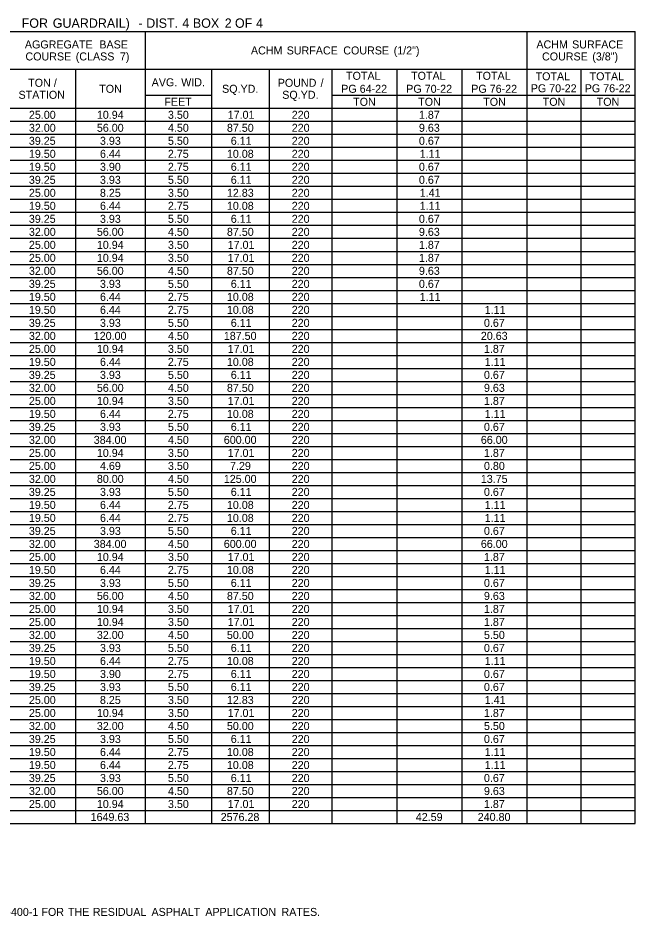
# Model space of a CAD drawing. Extents: x 540541 to 1930787, y -1948574 to 596640.
# Drawn here: x 558293 to 558755, y -1946901 to -1946228 of the extents above; entities that cross this region are included whole.
import ezdxf

# ---------------------------------------------------------------- set-up
doc = ezdxf.new("R2010")
doc.units = 0
doc.layers.add('Default', color=7, linetype='Continuous')

msp = doc.modelspace()

# ---------------------------------------------------------------- linework, layer by layer
at = {"layer": 'Default'}
for p, q in [((557868.72, -1946237.94), (558755.48, -1946237.94)), ((558388.4, -1946831.71), (558388.4, -1946237.94)), ((558674.56, -1946831.71), (558674.56, -1946237.94)), ((558755.48, -1946831.71), (558755.48, -1946237.94)), ((558286.51, -1946266.21), (558755.48, -1946266.21)), ((558336.23, -1946831.71), (558336.23, -1946266.21)), ((558438.12, -1946266.21), (558481.51, -1946266.21)), ((558438.12, -1946831.71), (558438.12, -1946266.21)), ((558481.51, -1946831.71), (558481.51, -1946266.21)), ((558528.31, -1946831.71), (558528.31, -1946266.21)), ((558577.06, -1946831.71), (558577.06, -1946266.21)), ((558625.81, -1946831.71), (558625.81, -1946266.21)), ((558715.02, -1946831.71), (558715.02, -1946266.21)), ((558388.4, -1946285.71), (558438.12, -1946285.71)), ((558388.4, -1946295.46), (558388.4, -1946285.71)), ((558438.12, -1946831.71), (558438.12, -1946285.71)), ((558528.31, -1946285.71), (558625.81, -1946285.71)), ((558625.81, -1946285.71), (558755.48, -1946285.71)), ((558286.51, -1946295.46), (558438.12, -1946295.46)), ((558336.23, -1946831.71), (558336.23, -1946295.46)), ((558438.12, -1946295.46), (558755.48, -1946295.46)), ((558481.51, -1946675.71), (558481.51, -1946295.46)), ((558577.06, -1946831.71), (558577.06, -1946295.46)), ((558625.81, -1946831.71), (558625.81, -1946295.46)), ((558090.05, -1946305.21), (558755.48, -1946305.21)), ((558090.05, -1946314.96), (558755.48, -1946314.96)), ((558090.05, -1946324.71), (558755.48, -1946324.71)), ((558040.32, -1946334.46), (558755.48, -1946334.46)), ((558090.05, -1946344.21), (558755.48, -1946344.21)), ((558090.05, -1946353.96), (558755.48, -1946353.96)), ((557868.72, -1946363.71), (558528.31, -1946363.71)), ((558090.05, -1946363.71), (558755.48, -1946363.71)), ((558090.05, -1946373.46), (558755.48, -1946373.46)), ((558090.05, -1946383.21), (558755.48, -1946383.21)), ((558090.05, -1946392.96), (558755.48, -1946392.96)), ((558040.32, -1946402.71), (558755.48, -1946402.71)), ((558090.05, -1946412.46), (558755.48, -1946412.46)), ((558090.05, -1946422.21), (558755.48, -1946422.21)), ((558090.05, -1946431.96), (558755.48, -1946431.96)), ((557868.72, -1946441.71), (558481.51, -1946441.71)), ((558040.32, -1946441.71), (558528.31, -1946441.71)), ((558481.51, -1946441.71), (558755.48, -1946441.71)), ((558090.05, -1946451.46), (558755.48, -1946451.46)), ((558090.05, -1946461.21), (558755.48, -1946461.21)), ((558090.05, -1946470.96), (558755.48, -1946470.96)), ((558040.32, -1946480.71), (558755.48, -1946480.71)), ((558090.05, -1946490.46), (558755.48, -1946490.46)), ((558090.05, -1946500.21), (558755.48, -1946500.21)), ((558090.05, -1946509.96), (558755.48, -1946509.96)), ((558040.32, -1946519.71), (558755.48, -1946519.71)), ((558090.05, -1946529.46), (558755.48, -1946529.46)), ((558090.05, -1946539.21), (558755.48, -1946539.21)), ((558090.05, -1946548.96), (558755.48, -1946548.96)), ((558040.32, -1946558.71), (558755.48, -1946558.71)), ((558090.05, -1946568.46), (558755.48, -1946568.46)), ((558090.05, -1946578.21), (558755.48, -1946578.21)), ((558090.05, -1946587.96), (558755.48, -1946587.96)), ((558040.32, -1946597.71), (558388.4, -1946597.71)), ((558336.23, -1946597.71), (558388.4, -1946597.71)), ((558388.4, -1946597.71), (558755.48, -1946597.71)), ((558090.05, -1946607.46), (558755.48, -1946607.46)), ((558090.05, -1946617.21), (558388.4, -1946617.21)), ((558336.23, -1946617.21), (558388.4, -1946617.21)), ((558388.4, -1946617.21), (558755.48, -1946617.21)), ((558090.05, -1946626.96), (558388.4, -1946626.96)), ((558336.23, -1946626.96), (558388.4, -1946626.96)), ((558388.4, -1946626.96), (558755.48, -1946626.96)), ((557868.72, -1946636.71), (558755.48, -1946636.71)), ((558040.32, -1946636.71), (558755.48, -1946636.71)), ((558090.05, -1946646.46), (558755.48, -1946646.46)), ((558090.05, -1946656.21), (558755.48, -1946656.21)), ((558090.05, -1946665.96), (558755.48, -1946665.96)), ((558040.32, -1946675.71), (558755.48, -1946675.71)), ((558090.05, -1946685.46), (558755.48, -1946685.46)), ((558090.05, -1946695.21), (558755.48, -1946695.21)), ((558481.51, -1946831.71), (558481.51, -1946695.21)), ((558090.05, -1946704.96), (558755.48, -1946704.96)), ((558040.32, -1946714.71), (558755.48, -1946714.71)), ((558090.05, -1946724.46), (558755.48, -1946724.46)), ((558090.05, -1946734.21), (558755.48, -1946734.21)), ((558040.32, -1946743.96), (558755.48, -1946743.96)), ((558090.05, -1946753.71), (558755.48, -1946753.71)), ((558090.05, -1946763.46), (558755.48, -1946763.46)), ((558090.05, -1946773.21), (558755.48, -1946773.21)), ((558040.32, -1946782.96), (558388.4, -1946782.96)), ((558336.23, -1946782.96), (558388.4, -1946782.96)), ((558388.4, -1946782.96), (558755.48, -1946782.96)), ((558090.05, -1946792.71), (558755.48, -1946792.71)), ((558090.05, -1946802.46), (558755.48, -1946802.46)), ((558090.05, -1946812.21), (558388.4, -1946812.21)), ((558336.23, -1946812.21), (558388.4, -1946812.21)), ((558388.4, -1946812.21), (558755.48, -1946812.21)), ((557868.72, -1946821.96), (558755.48, -1946821.96)), ((558090.05, -1946821.96), (558528.31, -1946821.96)), ((558388.4, -1946831.71), (558388.4, -1946821.96)), ((558528.31, -1946821.96), (558755.48, -1946821.96)), ((558674.56, -1946831.71), (558674.56, -1946821.96)), ((558090.05, -1946831.71), (558755.48, -1946831.71))]:
    msp.add_line(p, q, dxfattribs=at)

# ---------------------------------------------------------------- texts
for s, height, p in [(' FOR', 7, (558293.04, -1946235.1)), (' GUARDRAIL)', 7, (558316.36, -1946235.1)), (' DIST.', 7, (558386.41, -1946235.1)), (' 4', 7, (558413.45, -1946235.1)), (' BOX', 7, (558421.38, -1946235.1)), (' 2', 7, (558445.28, -1946235.1)), (' OF', 7, (558452.94, -1946235.1)), (' 4', 7, (558468.79, -1946235.1)), (' -', 7, (558380.51, -1946235.1)), ('AGGREGATE', 6, (558298.04, -1946250.58)), (' BASE', 6, (558351.66, -1946250.58)), (' (1/2")', 6, (558572.32, -1946255.08)), ('ACHM', 6, (558681.53, -1946250.58)), (' SURFACE', 6, (558706.08, -1946250.58)), ('COURSE', 6, (558298.49, -1946259.58)), (' (CLASS', 6, (558333.95, -1946259.58)), (' 7)', 6, (558367.07, -1946259.58)), ('ACHM', 6, (558467.54, -1946255.08)), (' SURFACE', 6, (558492.09, -1946255.08)), (' COURSE', 6, (558534.53, -1946255.08)), ('COURSE', 6, (558685.75, -1946259.58)), (' (3/8")', 6, (558721.2, -1946259.58)), ('TOTAL', 6, (558538.84, -1946274.09)), ('TOTAL', 6, (558587.59, -1946274.09)), ('TOTAL', 6, (558636.34, -1946274.09)), ('TOTAL', 6, (558680.94, -1946274.46)), ('TOTAL', 6, (558721.41, -1946274.46)), ('TON', 6, (558300.53, -1946279.34)), (' /', 6, (558317.55, -1946279.34)), ('AVG.', 6, (558393.11, -1946278.96)), (' WID.', 6, (558413.03, -1946278.96)), ('POUND', 6, (558487.64, -1946279.34)), (' /', 6, (558517.51, -1946279.34)), ('STATION', 6, (558293.31, -1946288.34)), ('TON', 6, (558353.8, -1946283.84)), ('SQ.YD.', 6, (558445.89, -1946283.84)), ('SQ.YD.', 6, (558490.99, -1946288.34)), ('PG', 6, (558535.21, -1946283.84)), (' 64-22', 6, (558546.82, -1946283.84)), ('PG', 6, (558583.96, -1946283.84)), (' 70-22', 6, (558595.57, -1946283.84)), ('PG', 6, (558632.71, -1946283.84)), (' 76-22', 6, (558644.32, -1946283.84)), ('PG', 6, (558677.32, -1946283.46)), (' 70-22', 6, (558688.92, -1946283.46)), ('PG', 6, (558717.78, -1946283.46)), (' 76-22', 6, (558729.39, -1946283.46)), ('FEET', 6, (558402.63, -1946293.59)), ('TON', 6, (558544.17, -1946293.59)), ('TON', 6, (558592.92, -1946293.59)), ('TON', 6, (558641.67, -1946293.59)), ('TON', 6, (558686.28, -1946293.59)), ('TON', 6, (558726.74, -1946293.59)), ('25.00', 6, (558301.09, -1946303.34)), ('10.94', 6, (558352.03, -1946303.34)), ('3.50', 6, (558405.31, -1946303.34)), ('17.01', 6, (558450.1, -1946303.34)), ('220', 6, (558498.12, -1946303.34)), ('1.87', 6, (558593.47, -1946303.34)), ('32.00', 6, (558301.09, -1946313.09)), ('56.00', 6, (558352.03, -1946313.09)), ('4.50', 6, (558405.31, -1946313.09)), ('87.50', 6, (558449.53, -1946313.09)), ('220', 6, (558498.12, -1946313.09)), ('9.63', 6, (558593.47, -1946313.09)), ('39.25', 6, (558301.05, -1946322.84)), ('3.93', 6, (558354.35, -1946322.84)), ('5.50', 6, (558405.31, -1946322.84)), ('6.11', 6, (558452.43, -1946322.84)), ('220', 6, (558498.12, -1946322.84)), ('0.67', 6, (558593.47, -1946322.84)), ('19.50', 6, (558301.09, -1946332.59)), ('6.44', 6, (558354.36, -1946332.59)), ('2.75', 6, (558405.27, -1946332.59)), ('10.08', 6, (558449.52, -1946332.59)), ('220', 6, (558498.12, -1946332.59)), ('1.11', 6, (558594.05, -1946332.59)), ('19.50', 6, (558301.09, -1946342.34)), ('3.90', 6, (558354.36, -1946342.34)), ('2.75', 6, (558405.27, -1946342.34)), ('6.11', 6, (558452.43, -1946342.34)), ('220', 6, (558498.12, -1946342.34)), ('0.67', 6, (558593.47, -1946342.34)), ('39.25', 6, (558301.05, -1946352.09)), ('3.93', 6, (558354.35, -1946352.09)), ('5.50', 6, (558405.31, -1946352.09)), ('6.11', 6, (558452.43, -1946352.09)), ('220', 6, (558498.12, -1946352.09)), ('0.67', 6, (558593.47, -1946352.09)), ('25.00', 6, (558301.09, -1946361.84)), ('8.25', 6, (558354.33, -1946361.84)), ('3.50', 6, (558405.31, -1946361.84)), ('12.83', 6, (558449.52, -1946361.84)), ('220', 6, (558498.12, -1946361.84)), ('1.41', 6, (558594.05, -1946361.84)), ('19.50', 6, (558301.09, -1946371.59)), ('6.44', 6, (558354.36, -1946371.59)), ('2.75', 6, (558405.27, -1946371.59)), ('10.08', 6, (558449.52, -1946371.59)), ('220', 6, (558498.12, -1946371.59)), ('1.11', 6, (558594.05, -1946371.59)), ('39.25', 6, (558301.05, -1946381.34)), ('3.93', 6, (558354.35, -1946381.34)), ('5.50', 6, (558405.31, -1946381.34)), ('6.11', 6, (558452.43, -1946381.34)), ('220', 6, (558498.12, -1946381.34)), ('0.67', 6, (558593.47, -1946381.34)), ('32.00', 6, (558301.09, -1946391.09)), ('56.00', 6, (558352.03, -1946391.09)), ('4.50', 6, (558405.31, -1946391.09)), ('87.50', 6, (558449.53, -1946391.09)), ('220', 6, (558498.12, -1946391.09)), ('9.63', 6, (558593.47, -1946391.09)), ('25.00', 6, (558301.09, -1946400.84)), ('10.94', 6, (558352.03, -1946400.84)), ('3.50', 6, (558405.31, -1946400.84)), ('17.01', 6, (558450.1, -1946400.84)), ('220', 6, (558498.12, -1946400.84)), ('1.87', 6, (558593.47, -1946400.84)), ('25.00', 6, (558301.09, -1946410.59)), ('10.94', 6, (558352.03, -1946410.59)), ('3.50', 6, (558405.31, -1946410.59)), ('17.01', 6, (558450.1, -1946410.59)), ('220', 6, (558498.12, -1946410.59)), ('1.87', 6, (558593.47, -1946410.59)), ('32.00', 6, (558301.09, -1946420.34)), ('56.00', 6, (558352.03, -1946420.34)), ('4.50', 6, (558405.31, -1946420.34)), ('87.50', 6, (558449.53, -1946420.34)), ('220', 6, (558498.12, -1946420.34)), ('9.63', 6, (558593.47, -1946420.34)), ('39.25', 6, (558301.05, -1946430.09)), ('3.93', 6, (558354.35, -1946430.09)), ('5.50', 6, (558405.31, -1946430.09)), ('6.11', 6, (558452.43, -1946430.09)), ('220', 6, (558498.12, -1946430.09)), ('0.67', 6, (558593.47, -1946430.09)), ('19.50', 6, (558301.09, -1946439.84)), ('6.44', 6, (558354.36, -1946439.84)), ('2.75', 6, (558405.27, -1946439.84)), ('10.08', 6, (558449.52, -1946439.84)), ('220', 6, (558498.12, -1946439.84)), ('1.11', 6, (558594.05, -1946439.84)), ('19.50', 6, (558301.09, -1946449.59)), ('6.44', 6, (558354.36, -1946449.59)), ('2.75', 6, (558405.27, -1946449.59)), ('10.08', 6, (558449.52, -1946449.59)), ('220', 6, (558498.12, -1946449.59)), ('1.11', 6, (558642.8, -1946449.59)), ('39.25', 6, (558301.05, -1946459.34)), ('3.93', 6, (558354.35, -1946459.34)), ('5.50', 6, (558405.31, -1946459.34)), ('6.11', 6, (558452.43, -1946459.34)), ('220', 6, (558498.12, -1946459.34)), ('0.67', 6, (558642.22, -1946459.34)), ('32.00', 6, (558301.09, -1946469.09)), ('120.00', 6, (558349.7, -1946469.09)), ('4.50', 6, (558405.31, -1946469.09)), ('187.50', 6, (558447.2, -1946469.09)), ('220', 6, (558498.12, -1946469.09)), ('20.63', 6, (558639.89, -1946469.09)), ('25.00', 6, (558301.09, -1946478.84)), ('10.94', 6, (558352.03, -1946478.84)), ('3.50', 6, (558405.31, -1946478.84)), ('17.01', 6, (558450.1, -1946478.84)), ('220', 6, (558498.12, -1946478.84)), ('1.87', 6, (558642.22, -1946478.84)), ('19.50', 6, (558301.09, -1946488.59)), ('6.44', 6, (558354.36, -1946488.59)), ('2.75', 6, (558405.27, -1946488.59)), ('10.08', 6, (558449.52, -1946488.59)), ('220', 6, (558498.12, -1946488.59)), ('1.11', 6, (558642.8, -1946488.59)), ('39.25', 6, (558301.05, -1946498.34)), ('3.93', 6, (558354.35, -1946498.34)), ('5.50', 6, (558405.31, -1946498.34)), ('6.11', 6, (558452.43, -1946498.34)), ('220', 6, (558498.12, -1946498.34)), ('0.67', 6, (558642.22, -1946498.34)), ('32.00', 6, (558301.09, -1946508.09)), ('56.00', 6, (558352.03, -1946508.09)), ('4.50', 6, (558405.31, -1946508.09)), ('87.50', 6, (558449.53, -1946508.09)), ('220', 6, (558498.12, -1946508.09)), ('9.63', 6, (558642.22, -1946508.09)), ('25.00', 6, (558301.09, -1946517.84)), ('10.94', 6, (558352.03, -1946517.84)), ('3.50', 6, (558405.31, -1946517.84)), ('17.01', 6, (558450.1, -1946517.84)), ('220', 6, (558498.12, -1946517.84)), ('1.87', 6, (558642.22, -1946517.84)), ('19.50', 6, (558301.09, -1946527.59)), ('6.44', 6, (558354.36, -1946527.59)), ('2.75', 6, (558405.27, -1946527.59)), ('10.08', 6, (558449.52, -1946527.59)), ('220', 6, (558498.12, -1946527.59)), ('1.11', 6, (558642.8, -1946527.59)), ('39.25', 6, (558301.05, -1946537.34)), ('3.93', 6, (558354.35, -1946537.34)), ('5.50', 6, (558405.31, -1946537.34)), ('6.11', 6, (558452.43, -1946537.34)), ('220', 6, (558498.12, -1946537.34)), ('0.67', 6, (558642.22, -1946537.34)), ('32.00', 6, (558301.09, -1946547.09)), ('384.00', 6, (558349.7, -1946547.09)), ('4.50', 6, (558405.31, -1946547.09)), ('600.00', 6, (558447.2, -1946547.09)), ('220', 6, (558498.12, -1946547.09)), ('66.00', 6, (558639.9, -1946547.09)), ('25.00', 6, (558301.09, -1946556.84)), ('10.94', 6, (558352.03, -1946556.84)), ('3.50', 6, (558405.31, -1946556.84)), ('17.01', 6, (558450.1, -1946556.84)), ('220', 6, (558498.12, -1946556.84)), ('1.87', 6, (558642.22, -1946556.84)), ('25.00', 6, (558301.09, -1946566.59)), ('4.69', 6, (558354.35, -1946566.59)), ('3.50', 6, (558405.31, -1946566.59)), ('7.29', 6, (558451.85, -1946566.59)), ('220', 6, (558498.12, -1946566.59)), ('0.80', 6, (558642.23, -1946566.59)), ('32.00', 6, (558301.09, -1946576.34)), ('80.00', 6, (558352.03, -1946576.34)), ('4.50', 6, (558405.31, -1946576.34)), ('125.00', 6, (558447.2, -1946576.34)), ('220', 6, (558498.12, -1946576.34)), ('13.75', 6, (558639.87, -1946576.34)), ('39.25', 6, (558301.05, -1946586.09)), ('3.93', 6, (558354.35, -1946586.09)), ('5.50', 6, (558405.31, -1946586.09)), ('6.11', 6, (558452.43, -1946586.09)), ('220', 6, (558498.12, -1946586.09)), ('0.67', 6, (558642.22, -1946586.09)), ('19.50', 6, (558301.09, -1946595.84)), ('6.44', 6, (558354.36, -1946595.84)), ('2.75', 6, (558405.27, -1946595.84)), ('10.08', 6, (558449.52, -1946595.84)), ('220', 6, (558498.12, -1946595.84)), ('1.11', 6, (558642.8, -1946595.84)), ('19.50', 6, (558301.09, -1946605.59)), ('6.44', 6, (558354.36, -1946605.59)), ('2.75', 6, (558405.27, -1946605.59)), ('10.08', 6, (558449.52, -1946605.59)), ('220', 6, (558498.12, -1946605.59)), ('1.11', 6, (558642.8, -1946605.59)), ('39.25', 6, (558301.05, -1946615.34)), ('3.93', 6, (558354.35, -1946615.34)), ('5.50', 6, (558405.31, -1946615.34)), ('6.11', 6, (558452.43, -1946615.34)), ('220', 6, (558498.12, -1946615.34)), ('0.67', 6, (558642.22, -1946615.34)), ('32.00', 6, (558301.09, -1946625.09)), ('384.00', 6, (558349.7, -1946625.09)), ('4.50', 6, (558405.31, -1946625.09)), ('600.00', 6, (558447.2, -1946625.09)), ('220', 6, (558498.12, -1946625.09)), ('66.00', 6, (558639.9, -1946625.09)), ('25.00', 6, (558301.09, -1946634.84)), ('10.94', 6, (558352.03, -1946634.84)), ('3.50', 6, (558405.31, -1946634.84)), ('17.01', 6, (558450.1, -1946634.84)), ('220', 6, (558498.12, -1946634.84)), ('1.87', 6, (558642.22, -1946634.84)), ('19.50', 6, (558301.09, -1946644.59)), ('6.44', 6, (558354.36, -1946644.59)), ('2.75', 6, (558405.27, -1946644.59)), ('10.08', 6, (558449.52, -1946644.59)), ('220', 6, (558498.12, -1946644.59)), ('1.11', 6, (558642.8, -1946644.59)), ('39.25', 6, (558301.05, -1946654.34)), ('3.93', 6, (558354.35, -1946654.34)), ('5.50', 6, (558405.31, -1946654.34)), ('6.11', 6, (558452.43, -1946654.34)), ('220', 6, (558498.12, -1946654.34)), ('0.67', 6, (558642.22, -1946654.34)), ('32.00', 6, (558301.09, -1946664.09)), ('56.00', 6, (558352.03, -1946664.09)), ('4.50', 6, (558405.31, -1946664.09)), ('87.50', 6, (558449.53, -1946664.09)), ('220', 6, (558498.12, -1946664.09)), ('9.63', 6, (558642.22, -1946664.09)), ('25.00', 6, (558301.09, -1946673.84)), ('10.94', 6, (558352.03, -1946673.84)), ('3.50', 6, (558405.31, -1946673.84)), ('17.01', 6, (558450.1, -1946673.84)), ('220', 6, (558498.12, -1946673.84)), ('1.87', 6, (558642.22, -1946673.84)), ('25.00', 6, (558301.09, -1946683.59)), ('10.94', 6, (558352.03, -1946683.59)), ('3.50', 6, (558405.31, -1946683.59)), ('17.01', 6, (558450.1, -1946683.59)), ('220', 6, (558498.12, -1946683.59)), ('1.87', 6, (558642.22, -1946683.59)), ('32.00', 6, (558301.09, -1946693.34)), ('32.00', 6, (558352.03, -1946693.34)), ('4.50', 6, (558405.31, -1946693.34)), ('50.00', 6, (558449.53, -1946693.34)), ('220', 6, (558498.12, -1946693.34)), ('5.50', 6, (558642.23, -1946693.34)), ('39.25', 6, (558301.05, -1946703.09)), ('3.93', 6, (558354.35, -1946703.09)), ('5.50', 6, (558405.31, -1946703.09)), ('6.11', 6, (558452.43, -1946703.09)), ('220', 6, (558498.12, -1946703.09)), ('0.67', 6, (558642.22, -1946703.09)), ('19.50', 6, (558301.09, -1946712.84)), ('6.44', 6, (558354.36, -1946712.84)), ('2.75', 6, (558405.27, -1946712.84)), ('10.08', 6, (558449.52, -1946712.84)), ('220', 6, (558498.12, -1946712.84)), ('1.11', 6, (558642.8, -1946712.84)), ('19.50', 6, (558301.09, -1946722.59)), ('3.90', 6, (558354.36, -1946722.59)), ('2.75', 6, (558405.27, -1946722.59)), ('6.11', 6, (558452.43, -1946722.59)), ('220', 6, (558498.12, -1946722.59)), ('0.67', 6, (558642.22, -1946722.59)), ('39.25', 6, (558301.05, -1946732.34)), ('3.93', 6, (558354.35, -1946732.34)), ('5.50', 6, (558405.31, -1946732.34)), ('6.11', 6, (558452.43, -1946732.34)), ('220', 6, (558498.12, -1946732.34)), ('0.67', 6, (558642.22, -1946732.34)), ('25.00', 6, (558301.09, -1946742.09)), ('8.25', 6, (558354.33, -1946742.09)), ('3.50', 6, (558405.31, -1946742.09)), ('12.83', 6, (558449.52, -1946742.09)), ('220', 6, (558498.12, -1946742.09)), ('1.41', 6, (558642.8, -1946742.09)), ('25.00', 6, (558301.09, -1946751.84)), ('10.94', 6, (558352.03, -1946751.84)), ('3.50', 6, (558405.31, -1946751.84)), ('17.01', 6, (558450.1, -1946751.84)), ('220', 6, (558498.12, -1946751.84)), ('1.87', 6, (558642.22, -1946751.84)), ('32.00', 6, (558301.09, -1946761.59)), ('32.00', 6, (558352.03, -1946761.59)), ('4.50', 6, (558405.31, -1946761.59)), ('50.00', 6, (558449.53, -1946761.59)), ('220', 6, (558498.12, -1946761.59)), ('5.50', 6, (558642.23, -1946761.59)), ('39.25', 6, (558301.05, -1946771.34)), ('3.93', 6, (558354.35, -1946771.34)), ('5.50', 6, (558405.31, -1946771.34)), ('6.11', 6, (558452.43, -1946771.34)), ('220', 6, (558498.12, -1946771.34)), ('0.67', 6, (558642.22, -1946771.34)), ('19.50', 6, (558301.09, -1946781.09)), ('6.44', 6, (558354.36, -1946781.09)), ('2.75', 6, (558405.27, -1946781.09)), ('10.08', 6, (558449.52, -1946781.09)), ('220', 6, (558498.12, -1946781.09)), ('1.11', 6, (558642.8, -1946781.09)), ('19.50', 6, (558301.09, -1946790.84)), ('6.44', 6, (558354.36, -1946790.84)), ('2.75', 6, (558405.27, -1946790.84)), ('10.08', 6, (558449.52, -1946790.84)), ('220', 6, (558498.12, -1946790.84)), ('1.11', 6, (558642.8, -1946790.84)), ('39.25', 6, (558301.05, -1946800.59)), ('3.93', 6, (558354.35, -1946800.59)), ('5.50', 6, (558405.31, -1946800.59)), ('6.11', 6, (558452.43, -1946800.59)), ('220', 6, (558498.12, -1946800.59)), ('0.67', 6, (558642.22, -1946800.59)), ('32.00', 6, (558301.09, -1946810.34)), ('56.00', 6, (558352.03, -1946810.34)), ('4.50', 6, (558405.31, -1946810.34)), ('87.50', 6, (558449.53, -1946810.34)), ('220', 6, (558498.12, -1946810.34)), ('9.63', 6, (558642.22, -1946810.34)), ('25.00', 6, (558301.09, -1946820.09)), ('10.94', 6, (558352.03, -1946820.09)), ('3.50', 6, (558405.31, -1946820.09)), ('17.01', 6, (558450.1, -1946820.09)), ('220', 6, (558498.12, -1946820.09)), ('1.87', 6, (558642.22, -1946820.09)), ('1649.63', 6, (558347.35, -1946829.84)), ('2576.28', 6, (558444.86, -1946829.84)), ('42.59', 6, (558591.14, -1946829.84)), ('240.80', 6, (558637.57, -1946829.84)), (' SS-400-1', 6, (558272.03, -1946901.01)), (' FOR', 6, (558308.23, -1946901.01)), (' THE', 6, (558328.14, -1946901.01)), (' RESIDUAL', 6, (558346.79, -1946901.01)), (' ASPHALT', 6, (558390.75, -1946901.01)), (' APPLICATION', 6, (558431.12, -1946901.01)), (' RATES.', 6, (558488.2, -1946901.01))]:
    msp.add_text(s, height=height, dxfattribs=at).set_placement(p)

doc.saveas('drawing.dxf')
